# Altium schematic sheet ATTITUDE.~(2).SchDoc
size A4
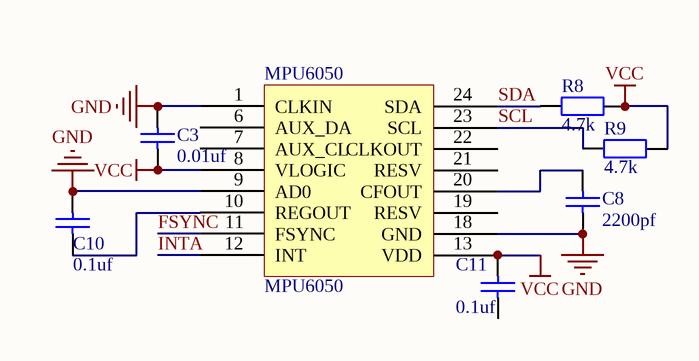
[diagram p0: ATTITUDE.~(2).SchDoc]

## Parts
C3  value 0.01uf  [C0805]  (hidden comment: 0.01)
C8  value 2200pf  [C0805]  (hidden comment: 2.2nF)
C10  value 0.1uf  [C0805]  (hidden comment: 104)
C11  value 0.1uf  [C0805]  (hidden comment: 104)
MPU6050  MPU6050  [MPU6050]
R8  4.7k  [6-0805_M]
R9  4.7k  [6-0805_M]

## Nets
GND: C3.1 C8.1 C10.1 MPU6050.1(CLKIN) MPU6050.9(AD0) MPU6050.18(GND)
VCC: C3.2 C11.1 MPU6050.8(VLOGIC) MPU6050.13(VDD) R8.1 R9.2
FSYNC: MPU6050.11(FSYNC)
INTA: MPU6050.12(INT)
SCL: MPU6050.23(SCL) R9.1
SDA: MPU6050.24(SDA) R8.2
NetC8_2: C8.2 MPU6050.20(CFOUT)
NetC10_2: C10.2 MPU6050.10(REGOUT)

Not connected (* = marked no-connect by the designer): C11 2; MPU6050 6(AUX_DA) 7(AUX_CL) 19(RESV) 21(RESV) 22(CLKOUT)

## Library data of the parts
C3 C8 C10 C11 = Cap Semi: Capacitor (Semiconductor SIM Model)
MPU6050 = Component_1
R8 R9 = Res2: Resistor; Value: 0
